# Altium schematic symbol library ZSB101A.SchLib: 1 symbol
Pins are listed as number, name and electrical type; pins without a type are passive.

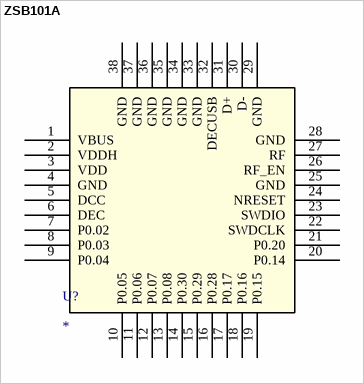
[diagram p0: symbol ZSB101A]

## ZSB101A
designator U?
pins: 1 VBUS, 2 VDDH, 3 VDD, 4 GND, 5 DCC, 6 DEC, 7 P0.02, 8 P0.03, 9 P0.04, 10 P0.05, 11 P0.06, 12 P0.07, 13 P0.08, 14 P0.30, 15 P0.29, 16 P0.28, 17 P0.17, 18 P0.16, 19 P0.15, 20 P0.14, 21 P0.20, 22 SWDCLK, 23 SWDIO, 24 NRESET, 25 GND, 26 RF_EN, 27 RF, 28 GND, 29 GND, 30 D-, 31 D+, 32 DECUSB, 33 GND, 34 GND, 35 GND, 36 GND, 37 GND, 38 GND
